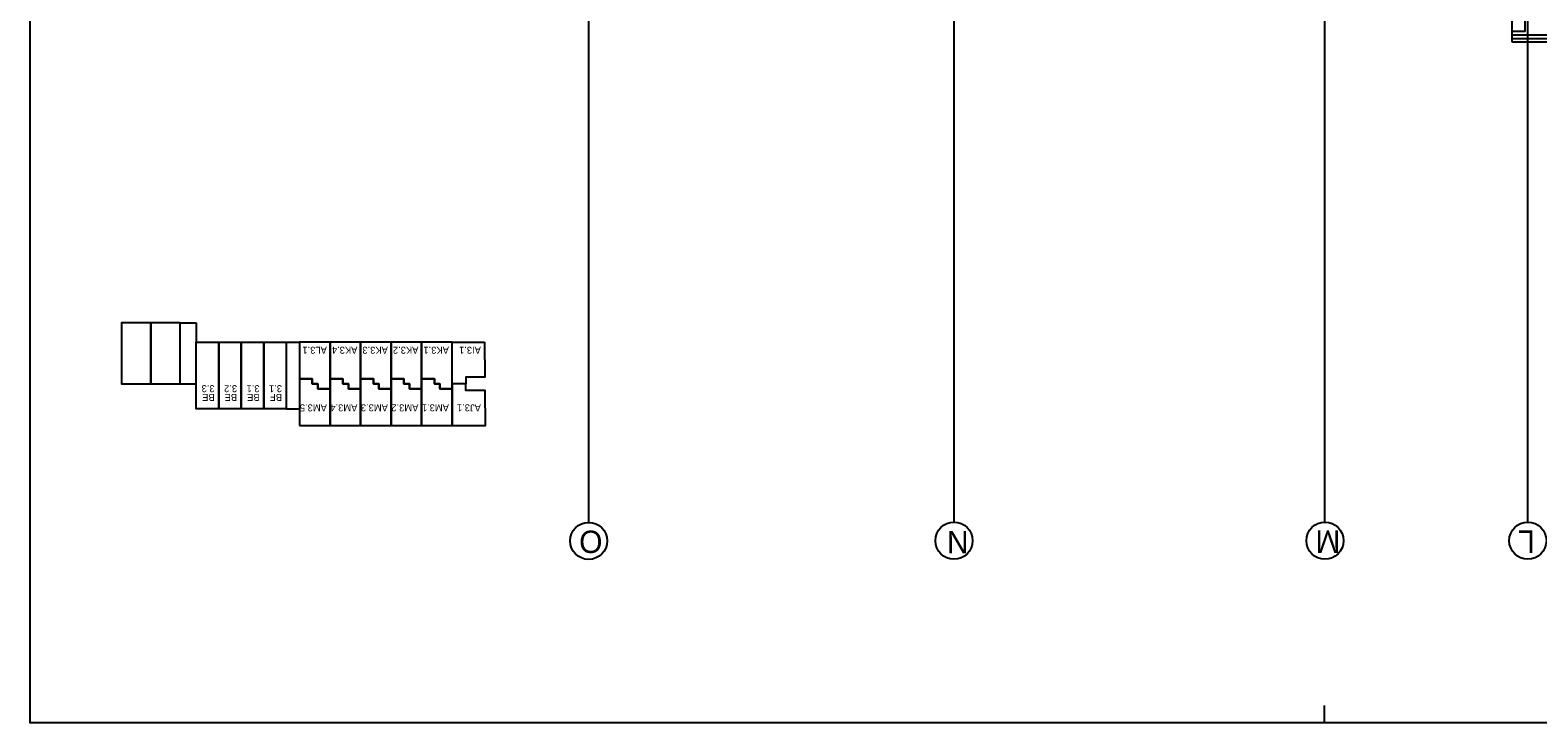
# Model space of a CAD drawing. Extents: x 1278 to 1356, y -253.7 to -224.
# Drawn here: x 1278.02 to 1299.56, y -253.66 to -243.76 of the extents above; entities that cross this region are included whole.
import ezdxf

# ---------------------------------------------------------------- set-up
doc = ezdxf.new("R2010")
doc.units = 0
for name, color, linetype in [('estrutura-eixos', 7, 'Continuous'), ('Level 2', 7, 'Continuous'), ('Level 40', 7, 'Continuous'), ('Level 62', 7, 'Continuous'), ('revestimentos', 7, 'Continuous'), ('vista', 7, 'Continuous')]:
    doc.layers.add(name, color=color, linetype=linetype)

msp = doc.modelspace()

# ---------------------------------------------------------------- linework, layer by layer
at = {"layer": 'estrutura-eixos'}
for p, q in [((1285.998, -225.567), (1285.998, -250.792)), ((1291.219, -225.567), (1291.219, -250.792)), ((1296.519, -250.792), (1296.519, -225.567)), ((1299.42, -250.792), (1299.42, -225.567))]:
    msp.add_line(p, q, dxfattribs=at)
at = {"layer": 'Level 2'}
for p, q in [((1299.193, -243.824), (1318.344, -243.824)), ((1299.193, -243.874), (1318.294, -243.874)), ((1299.193, -243.924), (1318.244, -243.924))]:
    msp.add_line(p, q, dxfattribs=at)
at = {"layer": 'Level 40'}
for p, q in [((1280.161, -247.94), (1280.391, -247.94)), ((1280.391, -247.94), (1280.391, -248.218)), ((1281.676, -248.218), (1281.866, -248.218)), ((1280.161, -248.812), (1280.391, -248.812)), ((1281.676, -249.169), (1281.866, -249.169))]:
    msp.add_line(p, q, dxfattribs=at)
for points in [[(1279.741, -247.94), (1279.32, -247.94), (1279.32, -248.812), (1279.741, -248.812)], [(1280.161, -247.94), (1279.741, -247.94), (1279.741, -248.812), (1280.161, -248.812)], [(1280.712, -249.169), (1280.391, -249.169), (1280.391, -248.218), (1280.712, -248.218)], [(1281.033, -249.169), (1280.712, -249.169), (1280.712, -248.218), (1281.033, -248.218)], [(1281.355, -249.169), (1281.033, -249.169), (1281.033, -248.218), (1281.355, -248.218)], [(1281.676, -249.169), (1281.355, -249.169), (1281.355, -248.218), (1281.676, -248.218)], [(1282.302, -248.218), (1281.866, -248.218), (1281.866, -248.741), (1282.049, -248.741), (1282.049, -248.812), (1282.128, -248.812), (1282.128, -248.884), (1282.302, -248.884)], [(1282.738, -248.218), (1282.302, -248.218), (1282.302, -248.741), (1282.485, -248.741), (1282.485, -248.812), (1282.564, -248.812), (1282.564, -248.884), (1282.738, -248.884)], [(1283.175, -248.218), (1282.738, -248.218), (1282.738, -248.741), (1282.921, -248.741), (1282.921, -248.812), (1283, -248.812), (1283, -248.884), (1283.175, -248.884)], [(1283.611, -248.218), (1283.175, -248.218), (1283.175, -248.741), (1283.357, -248.741), (1283.357, -248.812), (1283.436, -248.812), (1283.436, -248.884), (1283.611, -248.884)], [(1284.047, -248.218), (1283.611, -248.218), (1283.611, -248.741), (1283.793, -248.741), (1283.793, -248.812), (1283.873, -248.812), (1283.873, -248.884), (1284.047, -248.884)], [(1284.509, -248.218), (1284.516, -248.717), (1284.245, -248.717), (1284.245, -248.812), (1284.047, -248.812), (1284.047, -248.218)], [(1281.866, -249.407), (1282.302, -249.407), (1282.302, -248.884), (1282.128, -248.884), (1282.128, -248.812), (1282.049, -248.812), (1282.049, -248.741), (1281.866, -248.741)], [(1282.302, -249.407), (1282.738, -249.407), (1282.738, -248.884), (1282.564, -248.884), (1282.564, -248.812), (1282.485, -248.812), (1282.485, -248.741), (1282.302, -248.741)], [(1282.738, -249.407), (1283.175, -249.407), (1283.175, -248.884), (1283, -248.884), (1283, -248.812), (1282.921, -248.812), (1282.921, -248.741), (1282.738, -248.741)], [(1283.175, -249.407), (1283.611, -249.407), (1283.611, -248.884), (1283.436, -248.884), (1283.436, -248.812), (1283.357, -248.812), (1283.357, -248.741), (1283.175, -248.741)], [(1283.611, -249.407), (1284.047, -249.407), (1284.047, -248.884), (1283.873, -248.884), (1283.873, -248.812), (1283.793, -248.812), (1283.793, -248.741), (1283.611, -248.741)], [(1284.245, -248.812), (1284.047, -248.812), (1284.047, -249.407), (1284.526, -249.407), (1284.519, -248.908), (1284.245, -248.908)]]:
    msp.add_lwpolyline(points, close=True, dxfattribs=at)
for centre in [(1285.998, -251.058), (1291.219, -251.055), (1296.52, -251.055), (1299.419, -251.055)]:
    msp.add_circle(centre, 0.265, dxfattribs=at)
at = {"layer": 'Level 62'}
msp.add_lwpolyline([(1355.966, -223.959), (1355.966, -253.659), (1278.016, -253.659), (1278.016, -223.959)], close=True, dxfattribs=at)
at = {"layer": 'revestimentos'}
for p, q in [((1299.193, -232.094), (1299.193, -243.774)), ((1299.382, -243.774), (1299.382, -232.094)), ((1299.382, -243.774), (1299.193, -243.774))]:
    msp.add_line(p, q, dxfattribs=at)
at = {"layer": 'vista'}
for p, q in [((1299.193, -243.774), (1299.193, -243.924)), ((1296.516, -253.659), (1296.516, -253.409))]:
    msp.add_line(p, q, dxfattribs=at)

# ---------------------------------------------------------------- texts
at = {"layer": 'Level 40'}
for s, height, p in [('AL3.1', 0.1, (1282.257, -248.283)), ('AK3.4', 0.1, (1282.693, -248.283)), ('AK3.3', 0.1, (1283.129, -248.283)), ('AK3.2', 0.1, (1283.565, -248.283)), ('AK3.1', 0.1, (1284.001, -248.283)), ('AI3.1', 0.1, (1284.458, -248.283)), ('3.3', 0.1, (1280.653, -248.832)), ('3.2', 0.1, (1280.974, -248.832)), ('3.1', 0.1, (1281.295, -248.832)), ('3.1', 0.1, (1281.616, -248.832)), ('BE', 0.1, (1280.653, -248.957)), ('BE', 0.1, (1280.974, -248.957)), ('BE', 0.1, (1281.295, -248.957)), ('BF', 0.1, (1281.616, -248.957)), ('AM3.5', 0.1, (1282.257, -249.106)), ('AM3.4', 0.1, (1282.693, -249.106)), ('AM3.3', 0.1, (1283.129, -249.106)), ('AM3.2', 0.1, (1283.565, -249.106)), ('AM3.1', 0.1, (1284.001, -249.106)), ('AJ3.1', 0.1, (1284.458, -249.106)), ('O', 0.32, (1286.195, -250.911)), ('N', 0.32, (1291.427, -250.918)), ('M', 0.32, (1296.741, -250.909)), ('L', 0.32, (1299.519, -250.909))]:
    msp.add_text(s, height=height, rotation=180, dxfattribs=at).set_placement(p)

doc.saveas('drawing.dxf')
